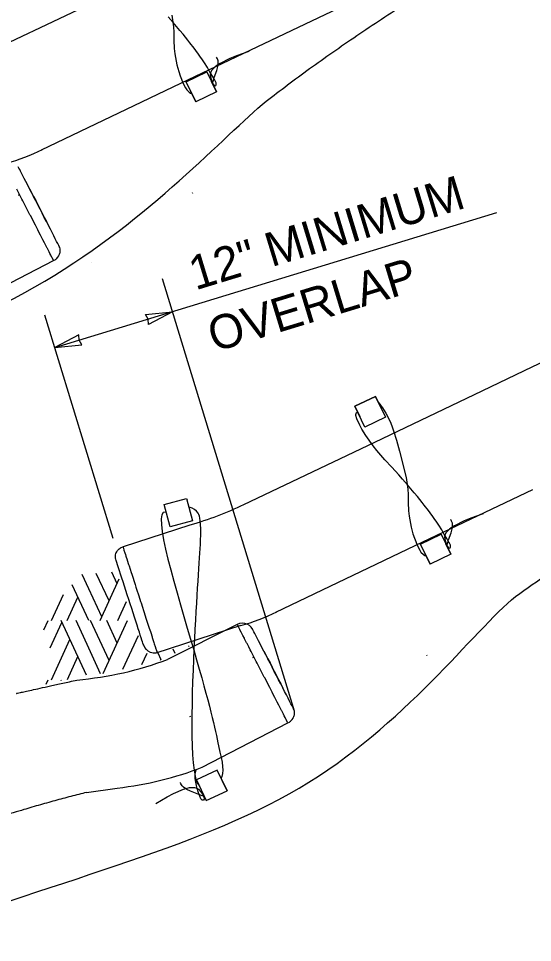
# Model space of a CAD drawing. Extents: x 99862 to 103680, y 99470 to 102076.
# Drawn here: x 100867.7 to 101109.4, y 101137.3 to 101571.3 of the extents above; entities that cross this region are included whole.
import ezdxf

# ---------------------------------------------------------------- set-up
doc = ezdxf.new("R2010")
doc.units = 0
for name, color, linetype in [('Level 10', 7, 'Continuous'), ('Level 11', 7, 'Continuous'), ('Level 15', 7, 'Continuous'), ('Level 17', 7, 'Continuous'), ('Level 20', 7, 'Continuous'), ('Level 4', 7, 'Continuous'), ('Level 6', 7, 'Continuous'), ('Level 8', 7, 'Continuous')]:
    doc.layers.add(name, color=color, linetype=linetype)

msp = doc.modelspace()

# ---------------------------------------------------------------- linework, layer by layer
at = {"layer": 'Level 10'}
for p, q in [((100867.69, 101488.62), (100867.89, 101488.23)), ((100867.69, 101488.62), (100867.69, 101488.62)), ((100949.7, 101489.08), (100949.52, 101489.48)), ((100977.85, 101271.47), (100978.06, 101271.08)), ((100977.85, 101271.47), (100977.85, 101271.47)), ((101059.87, 101271.93), (101059.69, 101272.33)), ((100948.22, 101243.73), (100948.4, 101243.33)), ((100948.22, 101243.73), (100948.4, 101243.33))]:
    msp.add_line(p, q, dxfattribs=at)
at = {"layer": 'Level 11'}
for p, q in [((100900.71, 101303.48), (100897.63, 101310.18)), ((100910.31, 101297.77), (100904.27, 101310.7)), ((100914.03, 101305.82), (100911.55, 101311.27)), ((100906.07, 101288.6), (100915.09, 101308.09)), ((100900.71, 101288.6), (100893, 101305.25)), ((100906.85, 101290.33), (100900.71, 101303.48)), ((100883.23, 101288.6), (100888.81, 101300.82)), ((100890.59, 101288.6), (100895.6, 101299.59)), ((100914.38, 101288.6), (100918.52, 101297.5)), ((100879.58, 101284.25), (100881.59, 101288.6)), ((100899.66, 101262.93), (100887.82, 101288.51)), ((100900.71, 101275.53), (100894.74, 101288.51)), ((100910.31, 101269.82), (100901.57, 101288.51)), ((100907.44, 101263.6), (100918.96, 101288.51)), ((100914.03, 101277.87), (100909.19, 101288.51)), ((100882.55, 101275.68), (100888.08, 101287.65)), ((100883.23, 101260.65), (100891.88, 101279.6)), ((100916.73, 101265.7), (100924.14, 101281.6)), ((100906.33, 101263.51), (100900.71, 101275.53)), ((100941.33, 101273.11), (100940.38, 101275.16)), ((100947.87, 101276.28), (100947.69, 101276.66)), ((100890.71, 101260.93), (100895.6, 101271.64)), ((100925.69, 101267.87), (100928.14, 101273.16)), ((100934.74, 101270.06), (100933.29, 101273.17)), ((100934.51, 101270.01), (100934.62, 101270.26)), ((100880.64, 101258.59), (100881.59, 101260.65)), ((100887.95, 101260.29), (100887.82, 101260.57))]:
    msp.add_line(p, q, dxfattribs=at)
at = {"layer": 'Level 15'}
for p, q in [((100884.79, 101416.72), (101092.65, 101480.15)), ((100997.43, 101245.93), (100935.44, 101449.06)), ((100912.15, 101327.07), (100880.12, 101432.02))]:
    msp.add_line(p, q, dxfattribs=at)
for points in [[(100940.15, 101433.61), (100928.84, 101427.58), (100928.67, 101430.11), (100927.4, 101432.3)], [(100884.79, 101416.72), (100897.55, 101418.03), (100896.27, 101420.22), (100896.11, 101422.75)]]:
    msp.add_lwpolyline(points, close=True, dxfattribs=at)
at = {"layer": 'Level 17'}
for points, degree in [([(100984.09, 101532.45), (101087.86, 101612.88), (101283.3, 101702.41)], 2), ([(100692.49, 101369.86), (100765.74, 101398.8), (100895.21, 101438.55), (100964.29, 101516.14), (100984.09, 101532.45)], 3), ([(101101.41, 101299.92), (101241.5, 101399.36), (101436.93, 101488.89)], 2), ([(100809.8, 101137.32), (100883.05, 101166.26), (101016.94, 101194.73), (101081.61, 101283.61), (101101.41, 101299.92)], 3)]:
    msp.add_open_spline(points, degree=degree, dxfattribs=at)
at = {"layer": 'Level 4'}
msp.add_line((100902.1, 101456.63), (100902.1, 101456.63), dxfattribs=at)
for points in [[(100975.96, 101555.78), (100970.21, 101553.76), (100967.13, 101552.52), (100962.55, 101550.25), (100960.95, 101549.23), (100960.11, 101548.58), (100958.88, 101547.38), (100958.48, 101546.82), (100957.99, 101545.79), (100957.85, 101544.86), (100958.11, 101543.29), (100958.71, 101541.41), (100959.06, 101540.61), (100959.75, 101539.83), (100960.24, 101539.76), (100960.45, 101539.85), (100960.67, 101540.16), (100960.61, 101541.05), (100960.04, 101542.28), (100959.62, 101543.02), (100958.88, 101544.23), (100958.09, 101545.53), (100957.7, 101546.18), (100956.53, 101548.24), (100955.15, 101550.53), (100954.21, 101551.96), (100953.03, 101553.66), (100952.33, 101554.62), (100951.14, 101556.22), (100950.26, 101557.37), (100948.32, 101559.86), (100947.28, 101561.17), (100945.08, 101563.89), (100943.55, 101565.75), (100940.41, 101569.45), (100938.06, 101572.14)], [(100939.84, 101572.9), (100940.54, 101567.47), (100940.69, 101564.92), (100940.72, 101563.52), (100940.71, 101561.1), (100940.91, 101557.26), (100941.21, 101554.66), (100941.48, 101552.94), (100942.16, 101549.56), (100943.01, 101546.35), (100943.65, 101544.36), (100945.05, 101540.84), (100946.19, 101538.73), (100946.77, 101537.88), (100947.93, 101536.65), (100948.5, 101536.29), (100949.14, 101536.16)], [(100958.84, 101540.9), (100959.37, 101542.34), (100959.75, 101543.66), (100960.89, 101546.83), (100961.4, 101548.71), (100961.6, 101550.56), (100961.52, 101551.42), (100961.19, 101552.45), (100960.9, 101552.9), (100960.72, 101553.08)], [(101037.02, 101390.85), (101037.07, 101390.82), (101037.59, 101390.21), (101037.92, 101389.74), (101038.83, 101388.44), (101040.41, 101385.9), (101041.3, 101384.25), (101042.7, 101381.25), (101043.4, 101379.51), (101044.09, 101377.59), (101045.46, 101373.23), (101046.86, 101368.15), (101050.01, 101355.75)], [(101086.12, 101338.63), (101080.37, 101336.62), (101077.29, 101335.37), (101072.72, 101333.1), (101071.12, 101332.08), (101070.27, 101331.43), (101069.05, 101330.23), (101068.64, 101329.67), (101068.16, 101328.64), (101068.01, 101327.71), (101068.28, 101326.14), (101068.88, 101324.26), (101069.23, 101323.46), (101069.92, 101322.68), (101070.41, 101322.61), (101070.62, 101322.7), (101070.83, 101323.01), (101070.77, 101323.9), (101070.21, 101325.13), (101069.79, 101325.87), (101069.05, 101327.09), (101068.25, 101328.38), (101067.86, 101329.04), (101066.7, 101331.1), (101065.32, 101333.38), (101064.38, 101334.81), (101063.19, 101336.51), (101062.5, 101337.47), (101061.31, 101339.07), (101060.43, 101340.22), (101058.49, 101342.71), (101057.45, 101344.02), (101055.24, 101346.75), (101053.71, 101348.6), (101050.58, 101352.3), (101048.23, 101354.99), (101046.5, 101356.92), (101043.16, 101360.55), (101040.01, 101363.97), (101036.17, 101368.35), (101034.43, 101370.53), (101031, 101375.42), (101029.16, 101378.47), (101028.17, 101380.32), (101026.8, 101383.32), (101026.37, 101384.83), (101026.34, 101385.38), (101026.64, 101386.19), (101027.07, 101386.6), (101027.08, 101386.6)], [(101050.01, 101355.75), (101050.71, 101350.32), (101050.86, 101347.77), (101050.88, 101346.38), (101050.88, 101343.95), (101051.08, 101340.11), (101051.38, 101337.51), (101051.65, 101335.79), (101052.33, 101332.41), (101053.18, 101329.2), (101053.81, 101327.21), (101055.22, 101323.69), (101056.35, 101321.58), (101056.93, 101320.73), (101058.09, 101319.5), (101058.67, 101319.14), (101059.3, 101319.01)], [(101069.01, 101323.75), (101069.54, 101325.19), (101069.92, 101326.51), (101071.06, 101329.69), (101071.56, 101331.56), (101071.76, 101333.41), (101071.69, 101334.27), (101071.35, 101335.3), (101071.07, 101335.75), (101070.89, 101335.93)], [(100932.32, 101202.68), (100937.59, 101205.74), (100940.54, 101207.28), (100945.23, 101209.28), (100947.05, 101209.83), (100948.09, 101210.06), (100949.8, 101210.2), (100950.49, 101210.15), (100951.59, 101209.85), (100952.39, 101209.35), (100953.41, 101208.13), (100954.45, 101206.46), (100954.83, 101205.67), (100954.98, 101204.64), (100954.71, 101204.22), (100954.51, 101204.12), (100954.13, 101204.16), (100953.5, 101204.78), (100952.92, 101206.01), (100952.64, 101206.81), (100952.19, 101208.16), (100951.72, 101209.61), (100951.48, 101210.33), (100951.13, 101212.56), (100950.83, 101214.39), (100950.7, 101216.65), (100951.29, 101218.32)], [(100954.38, 101206.13), (100952.94, 101206.66), (100951.7, 101207.22), (100948.54, 101208.42), (100946.79, 101209.26), (100945.25, 101210.3), (100944.65, 101210.92), (100944.08, 101211.84), (100943.92, 101212.35), (100943.91, 101212.51)]]:
    msp.add_lwpolyline(points, dxfattribs=at)
for points in [[(100936.81, 101339.41), (100929.81, 101340.98), (100955.23, 101260.26), (100962.47, 101226.34), (100964.65, 101216.95), (100962.81, 101214.25)], [(100953.01, 101210.7), (100948.18, 101213.44), (100950.12, 101285.33), (100954.34, 101332.82), (100952.36, 101339.75), (100950, 101341.14), (100947.94, 101341.73)]]:
    msp.add_open_spline(points, degree=3, dxfattribs=at)
at = {"layer": 'Level 6'}
for p, q in [((100956.28, 101546.26), (100946.53, 101541.61)), ((100960.79, 101536.82), (100958.47, 101541.68)), ((100948.72, 101537.03), (100951.04, 101532.17)), ((100960.78, 101536.82), (100951.03, 101532.17)), ((101035.6, 101393.82), (101025.85, 101389.17)), ((101025.86, 101389.16), (101035.61, 101393.81)), ((101035.6, 101393.82), (101035.61, 101393.81)), ((101037.92, 101388.95), (101035.6, 101393.82)), ((101035.6, 101393.81), (101035.6, 101393.81)), ((101035.61, 101393.81), (101040.24, 101384.08)), ((101025.86, 101389.16), (101025.85, 101389.17)), ((101025.85, 101389.17), (101028.17, 101384.31)), ((101025.86, 101389.16), (101025.85, 101389.16)), ((101030.49, 101379.43), (101025.86, 101389.16)), ((101040.24, 101384.08), (101030.49, 101379.43)), ((101040.24, 101384.08), (101040.24, 101384.08)), ((101030.49, 101379.43), (101030.49, 101379.43)), ((100936.26, 101343.05), (100946.7, 101345.83)), ((100946.7, 101345.83), (100949.48, 101335.4)), ((100947.39, 101345.37), (100947.39, 101345.37)), ((100939.04, 101332.62), (100936.26, 101343.05)), ((100949.48, 101335.4), (100939.04, 101332.62)), ((101066.45, 101329.11), (101056.7, 101324.47)), ((101070.95, 101319.67), (101068.64, 101324.53)), ((101058.89, 101319.88), (101061.2, 101315.02)), ((101070.95, 101319.67), (101061.2, 101315.03)), ((100961.17, 101218.34), (100951.38, 101213.76)), ((100965.75, 101208.56), (100961.17, 101218.34)), ((100951.38, 101213.76), (100955.97, 101203.98)), ((100965.75, 101208.55), (100963.46, 101213.43)), ((100963.46, 101213.43), (100965.75, 101208.56)), ((100955.97, 101203.97), (100965.75, 101208.55))]:
    msp.add_line(p, q, dxfattribs=at)
for points in [[(100956.28, 101546.26), (100960.78, 101536.82), (100960.79, 101536.82), (100951.04, 101532.17), (100951.03, 101532.17), (100946.53, 101541.61), (100956.28, 101546.26)], [(100956.28, 101546.26), (100956.28, 101546.26), (100960.79, 101536.82), (100960.79, 101536.82)], [(100951.04, 101532.17), (100951.04, 101532.17), (100946.53, 101541.61), (100946.53, 101541.61)], [(100958.47, 101541.68), (100960.79, 101536.82), (100960.79, 101536.82)], [(100951.04, 101532.17), (100951.04, 101532.17), (100948.72, 101537.03)], [(101035.6, 101393.81), (101037.92, 101388.95), (101037.92, 101388.95)], [(101035.6, 101393.81), (101035.6, 101393.81), (101035.6, 101393.81)], [(101028.17, 101384.31), (101028.17, 101384.31), (101025.85, 101389.16)], [(101025.85, 101389.16), (101025.85, 101389.16), (101025.85, 101389.16)], [(101066.45, 101329.11), (101070.95, 101319.67), (101070.95, 101319.67), (101061.2, 101315.02), (101061.2, 101315.03), (101056.7, 101324.47), (101066.45, 101329.11)], [(101066.45, 101329.11), (101066.45, 101329.11), (101070.95, 101319.67), (101070.95, 101319.67)], [(101061.2, 101315.02), (101061.2, 101315.02), (101056.7, 101324.47), (101056.7, 101324.47)], [(101068.64, 101324.53), (101070.95, 101319.67), (101070.95, 101319.67)], [(101061.2, 101315.02), (101061.2, 101315.02), (101058.89, 101319.88)]]:
    msp.add_lwpolyline(points, dxfattribs=at)
at = {"layer": 'Level 8'}
for p, q in [((100872.89, 101491.38), (100873.81, 101489.58)), ((100873.81, 101489.58), (100874.78, 101487.7)), ((100874.78, 101487.7), (100875.78, 101485.76)), ((100875.78, 101485.76), (100876.77, 101483.84)), ((100876.77, 101483.84), (100876.8, 101483.78)), ((100876.8, 101483.78), (100877.82, 101481.8)), ((100878.84, 101479.82), (100879.84, 101477.86)), ((100879.84, 101477.86), (100880.82, 101475.96)), ((100880.82, 101475.96), (100881.77, 101474.12)), ((100983.05, 101274.23), (100983.98, 101272.43)), ((100983.98, 101272.43), (100984.95, 101270.55)), ((100984.95, 101270.55), (100985.95, 101268.61)), ((100985.95, 101268.61), (100986.93, 101266.69)), ((100986.93, 101266.69), (100986.96, 101266.64)), ((100986.96, 101266.64), (100987.98, 101264.65)), ((100989, 101262.67), (100990.01, 101260.71)), ((100990.01, 101260.71), (100990.99, 101258.81)), ((100990.99, 101258.81), (100991.93, 101256.97))]:
    msp.add_line(p, q, dxfattribs=at)
for points in [[(101126.79, 101627.97), (101017.92, 101576.06), (100999.22, 101567.15)], [(100863.53, 101560.23), (100925, 101589.54), (100975.51, 101613.62)], [(100999.22, 101567.15), (100947.44, 101542.46), (100878.32, 101509.51)], [(100843.9, 101436.84), (100884.21, 101457.58), (100884.9, 101457.99), (100885.21, 101458.24), (100885.53, 101458.49), (100885.65, 101458.6), (100886.07, 101459.06), (100886.19, 101459.18), (100886.63, 101459.82), (100886.71, 101459.96), (100886.74, 101460.02), (100887.03, 101460.64), (100887.15, 101461.06), (100887.24, 101461.35), (100887.27, 101461.5), (100887.33, 101462.13), (100887.34, 101462.22), (100887.29, 101462.93), (100887.26, 101463.08), (100887.23, 101463.19), (100887.07, 101463.76), (100886.88, 101464.18), (100886.6, 101464.73), (100886.16, 101465.59), (100885.62, 101466.64), (100884.99, 101467.85), (100884.29, 101469.23), (100883.51, 101470.74), (100882.67, 101472.38), (100881.77, 101474.12), (100880.82, 101475.96), (100879.84, 101477.86), (100878.84, 101479.82), (100877.82, 101481.8), (100876.8, 101483.78), (100875.78, 101485.76), (100874.78, 101487.7), (100873.81, 101489.58), (100872.89, 101491.38), (100872.01, 101493.09), (100871.19, 101494.69), (100870.43, 101496.15), (100869.76, 101497.47), (100869.16, 101498.62), (100868.66, 101499.6), (100868.25, 101500.4), (100867.93, 101501), (100867.73, 101501.41), (100867.62, 101501.61)], [(100884.21, 101457.58), (100884.08, 101457.83), (100883.52, 101458.91), (100883.44, 101459.07), (100882.85, 101460.22), (100882.45, 101460.99), (100882.07, 101461.74), (100881.28, 101463.28), (100881.18, 101463.45), (100880.21, 101465.35), (100879.91, 101465.93), (100879.16, 101467.39), (100878.4, 101468.87), (100878.03, 101469.58), (100876.85, 101471.87), (100876.77, 101472.02), (100875.63, 101474.25), (100875.06, 101475.36), (100874.37, 101476.69), (100873.3, 101478.78), (100873.1, 101479.17), (100871.82, 101481.65), (100871.52, 101482.23), (100870.55, 101484.12), (100869.77, 101485.63), (100869.3, 101486.54), (100868.09, 101488.89), (100866.93, 101491.15)], [(100877.82, 101481.8), (100878.27, 101480.93), (100878.84, 101479.82)], [(101085.68, 101396.47), (101105.64, 101405.99), (101206.89, 101454.26)], [(100973.69, 101343.08), (101035.16, 101372.39), (101085.68, 101396.47)], [(101109.38, 101350), (101057.61, 101325.31), (100988.49, 101292.36)], [(100926.58, 101276.98), (100926.35, 101277.47), (100926.21, 101277.9), (100926, 101278.55), (100925.72, 101279.4), (100925.38, 101280.45), (100924.98, 101281.69), (100924.52, 101283.1), (100924.01, 101284.66), (100923.46, 101286.37), (100922.87, 101288.2), (100922.24, 101290.13), (100921.59, 101292.14), (100920.92, 101294.21), (100920.23, 101296.32), (100919.54, 101298.45), (100918.85, 101300.57), (100918.18, 101302.66), (100917.52, 101304.7), (100916.88, 101306.66), (100916.27, 101308.53), (100915.71, 101310.28), (100915.18, 101311.9), (100914.71, 101313.37), (100914.28, 101314.67), (100913.92, 101315.78), (100913.62, 101316.71), (100913.43, 101317.3), (100913.31, 101317.74), (100913.25, 101318.33), (100913.23, 101318.44), (100913.23, 101318.6), (100913.3, 101319.3), (100913.32, 101319.39), (100913.48, 101320.01), (100913.54, 101320.14), (100913.67, 101320.42), (100913.86, 101320.81), (100914.25, 101321.38), (100914.28, 101321.44), (100914.38, 101321.56), (100914.92, 101322.12), (100915.05, 101322.22), (100915.54, 101322.6), (100915.69, 101322.7), (100916.03, 101322.89), (100916.38, 101323.08), (100917.13, 101323.38), (100948.45, 101333.46)], [(100916.76, 101323.23), (100916.85, 101322.96), (100917.22, 101321.8), (100917.28, 101321.64), (100917.68, 101320.41), (100917.94, 101319.58), (100918.2, 101318.78), (100918.74, 101317.14), (100918.8, 101316.95), (100919.45, 101314.92), (100919.66, 101314.3), (100920.16, 101312.73), (100920.67, 101311.16), (100920.92, 101310.4), (100921.72, 101307.95), (100921.77, 101307.78), (100922.54, 101305.4), (100922.93, 101304.21), (100923.39, 101302.79), (100924.11, 101300.55), (100924.25, 101300.14), (100925.11, 101297.48), (100925.31, 101296.86), (100925.97, 101294.84), (100926.49, 101293.23), (100926.81, 101292.25), (100927.62, 101289.73), (100928.41, 101287.32), (100928.7, 101286.4), (100929.15, 101285.03), (100929.69, 101283.35), (100929.84, 101282.9), (100930.47, 101280.95), (100930.58, 101280.63), (100931.04, 101279.19), (100931.33, 101278.31), (100931.54, 101277.64), (100931.95, 101276.38), (100931.97, 101276.33), (100932.32, 101275.26), (100932.41, 101274.98), (100932.58, 101274.45), (100932.71, 101274.05), (100932.75, 101273.91), (100932.84, 101273.64)], [(100972.25, 101286.17), (100932.2, 101273.27)], [(100971.68, 101287.18), (100970.55, 101286.76), (100937.82, 101270.27)], [(100954.07, 101219.69), (100994.37, 101240.43), (100995.07, 101240.84), (100995.38, 101241.09), (100995.69, 101241.34), (100995.82, 101241.45), (100996.24, 101241.91), (100996.35, 101242.04), (100996.8, 101242.67), (100996.87, 101242.81), (100996.9, 101242.87), (100997.2, 101243.5), (100997.32, 101243.91), (100997.4, 101244.21), (100997.43, 101244.35), (100997.49, 101244.99), (100997.5, 101245.07), (100997.45, 101245.78), (100997.43, 101245.93), (100997.4, 101246.04), (100997.24, 101246.61), (100997.05, 101247.03), (100996.77, 101247.58), (100996.32, 101248.45), (100995.78, 101249.49), (100995.16, 101250.71), (100994.45, 101252.08), (100993.67, 101253.59), (100992.83, 101255.23), (100991.93, 101256.97), (100990.99, 101258.81), (100990.01, 101260.71), (100989, 101262.67), (100987.98, 101264.65), (100986.96, 101266.64), (100985.95, 101268.61), (100984.95, 101270.55), (100983.98, 101272.43), (100983.05, 101274.23), (100982.17, 101275.94), (100981.35, 101277.54), (100980.6, 101279), (100979.92, 101280.32), (100979.33, 101281.47), (100978.82, 101282.45), (100978.41, 101283.25), (100978.1, 101283.86), (100977.89, 101284.26), (100977.79, 101284.46)], [(100994.37, 101240.43), (100994.24, 101240.68), (100993.69, 101241.77), (100993.61, 101241.92), (100993.01, 101243.07), (100992.62, 101243.84), (100992.23, 101244.59), (100991.44, 101246.13), (100991.35, 101246.31), (100990.38, 101248.2), (100990.08, 101248.78), (100989.32, 101250.24), (100988.57, 101251.72), (100988.2, 101252.43), (100987.02, 101254.72), (100986.94, 101254.87), (100985.8, 101257.1), (100985.23, 101258.21), (100984.54, 101259.54), (100983.46, 101261.63), (100983.26, 101262.02), (100981.99, 101264.5), (100981.69, 101265.08), (100980.72, 101266.97), (100979.94, 101268.48), (100979.47, 101269.39), (100978.26, 101271.75), (100977.1, 101274), (100976.66, 101274.86), (100976, 101276.14), (100975.19, 101277.71), (100974.97, 101278.13), (100974.03, 101279.96), (100973.88, 101280.26), (100973.19, 101281.6), (100972.76, 101282.43), (100972.44, 101283.05), (100971.84, 101284.23), (100971.81, 101284.28), (100971.3, 101285.27), (100971.16, 101285.54), (100970.91, 101286.03), (100970.72, 101286.4), (100970.65, 101286.54), (100970.52, 101286.79)], [(100977.84, 101284.36), (100977.16, 101285.36), (100976.28, 101286.18), (100975.23, 101286.79), (100974.08, 101287.15), (100972.87, 101287.24), (100971.68, 101287.18)], [(100932.2, 101273.27), (100930.99, 101273.3), (100929.82, 101273.59), (100928.74, 101274.14), (100927.81, 101274.92), (100927.08, 101275.88), (100926.58, 101276.98)], [(100987.98, 101264.65), (100988.43, 101263.78), (100989, 101262.67)], [(100899.72, 101207.78), (100914.14, 101209.89)]]:
    msp.add_lwpolyline(points, dxfattribs=at)
for centre, radius, start, end in [((100832.21, 101607.11), 108, 286.0586, 295.6739), ((100901.8, 101493.7), 166.89, 286.2326, 295.5163), ((100942.37, 101389.96), 108, 286.0586, 295.6739)]:
    msp.add_arc(centre, radius, start, end, dxfattribs=at)
for centre, major_axis, ratio, start_param, end_param in [((100879.26, 101357.01), (130.13, 0), 0.746461, 4.834507, 5.179106), ((100895.65, 101306.63), (127.68, 0), 0.765805, 4.85769, 5.187618)]:
    msp.add_ellipse(centre, major_axis=major_axis, ratio=ratio, start_param=start_param, end_param=end_param, dxfattribs=at)
for points in [[(100866.84, 101254.34), (100866.84, 101254.34), (100895.12, 101260.58)], [(100899.72, 101207.78), (100866.61, 101199.66), (100825.69, 101185.19)]]:
    msp.add_open_spline(points, degree=2, dxfattribs=at)

# ---------------------------------------------------------------- texts
at = {"layer": 'Level 20'}
for s, p in [('12" MINIMUM ', (100950.88, 101443.58)), ('OVERLAP', (100959.75, 101414.5))]:
    msp.add_text(s, height=16, rotation=16.9721, dxfattribs=at).set_placement(p)

doc.saveas('drawing.dxf')
